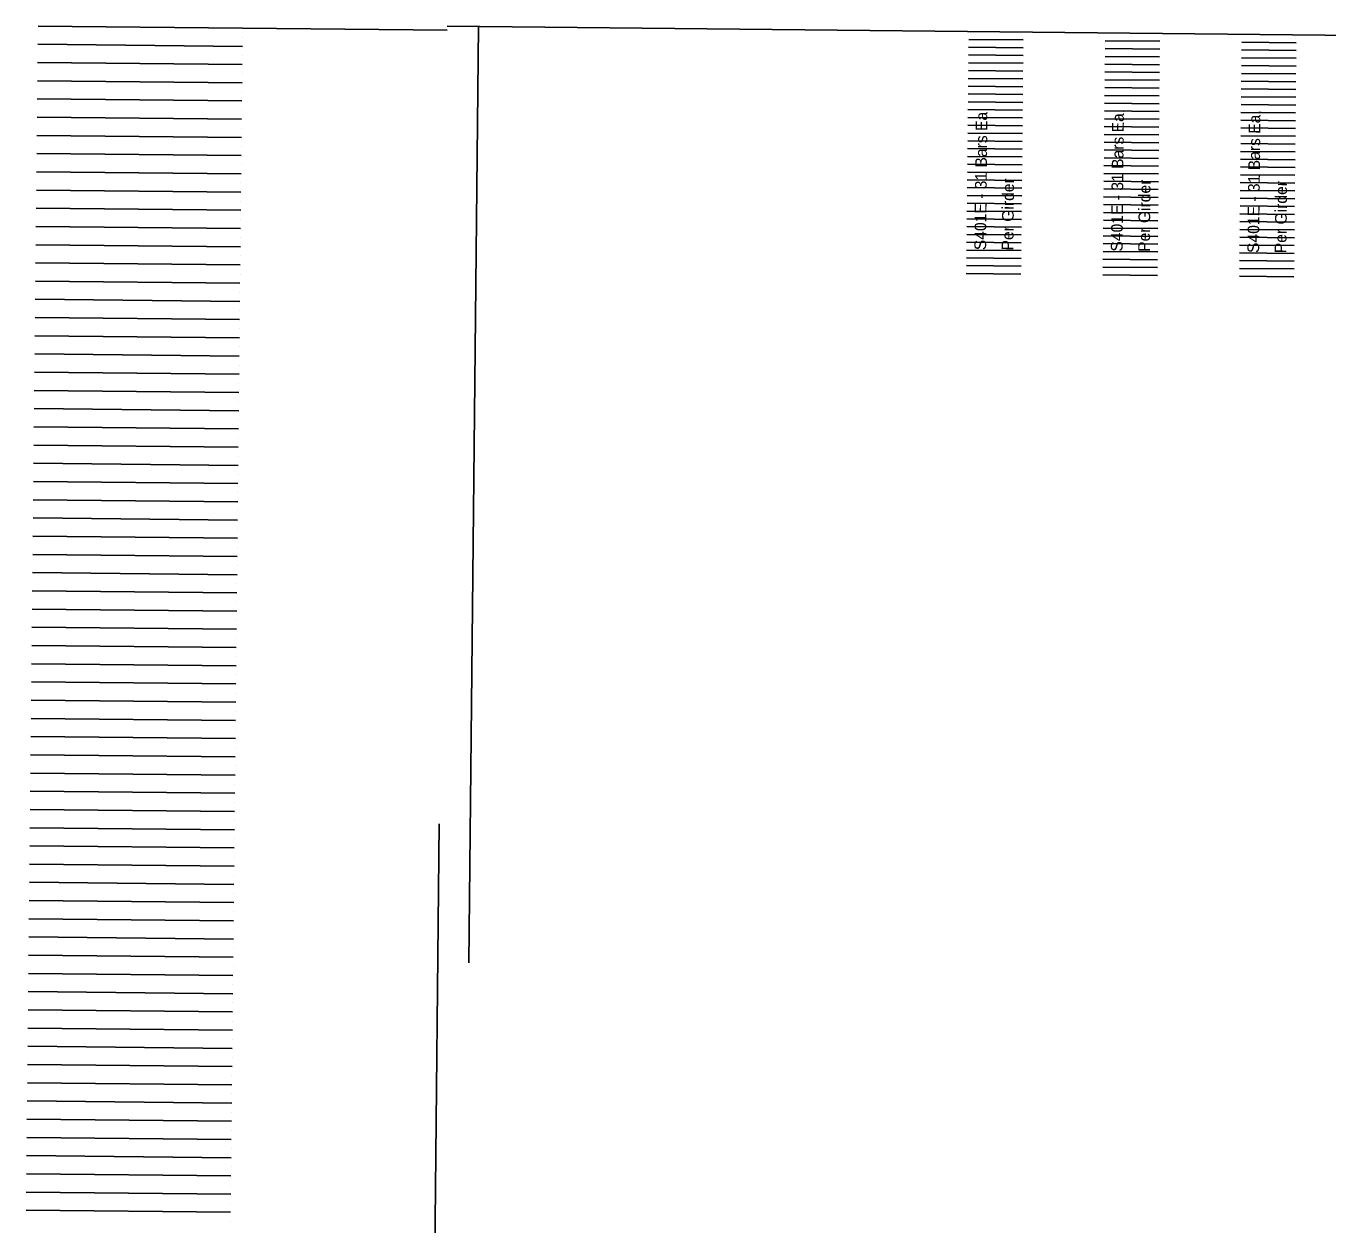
# Model space of a CAD drawing. Extents: x 632547 to 633311, y 380830 to 386139.
# Drawn here: x 633073.6 to 633157.1, y 381343.8 to 381420.6 of the extents above; entities that cross this region are included whole.
import ezdxf

# ---------------------------------------------------------------- set-up
doc = ezdxf.new("R2010")
doc.units = 0
for name, color, linetype in [('B_Border', 7, 'Continuous'), ('R_Border_Scale', 7, 'Continuous'), ('R_Wall', 7, 'Continuous')]:
    doc.layers.add(name, color=color, linetype=linetype)

msp = doc.modelspace()

# ---------------------------------------------------------------- linework, layer by layer
at = {"layer": 'B_Border'}
msp.add_line((633217.685, 381419.389), (633100.631, 381420.573), dxfattribs=at)
at = {"layer": 'R_Border_Scale'}
for p, q in [((633087.518, 381420.455), (633074.406, 381420.588)), ((633100.629, 381420.323), (633087.518, 381420.455)), ((633087.518, 381420.455), (633087.518, 381420.455)), ((633102.631, 381420.552), (633102.024, 381360.555)), ((633087.512, 381419.872), (633087.512, 381419.872)), ((633137.559, 381419.699), (633134.059, 381419.735)), ((633146.309, 381419.611), (633142.809, 381419.646)), ((633087.506, 381419.288), (633074.395, 381419.421)), ((633087.506, 381419.288), (633087.506, 381419.288)), ((633137.549, 381418.699), (633134.049, 381418.735)), ((633137.554, 381419.199), (633134.054, 381419.235)), ((633146.304, 381419.111), (633142.804, 381419.146)), ((633155.053, 381419.022), (633151.553, 381419.058)), ((633155.058, 381419.522), (633151.559, 381419.558)), ((633087.494, 381418.121), (633074.383, 381418.253)), ((633087.494, 381418.121), (633087.494, 381418.121)), ((633087.5, 381418.704), (633087.5, 381418.704)), ((633137.544, 381418.199), (633134.044, 381418.235)), ((633146.294, 381418.111), (633142.794, 381418.146)), ((633146.299, 381418.611), (633142.799, 381418.646)), ((633155.043, 381418.022), (633151.543, 381418.058)), ((633155.048, 381418.522), (633151.548, 381418.558)), ((633087.482, 381416.953), (633074.371, 381417.086)), ((633087.488, 381417.537), (633087.488, 381417.537)), ((633137.534, 381417.199), (633134.034, 381417.235)), ((633137.539, 381417.699), (633134.039, 381417.735)), ((633146.283, 381417.111), (633142.784, 381417.146)), ((633146.289, 381417.611), (633142.789, 381417.646)), ((633155.038, 381417.522), (633151.538, 381417.558)), ((633087.476, 381416.37), (633087.476, 381416.37)), ((633087.482, 381416.953), (633087.482, 381416.953)), ((633137.524, 381416.199), (633134.024, 381416.235)), ((633137.529, 381416.699), (633134.029, 381416.735)), ((633146.278, 381416.611), (633142.779, 381416.646)), ((633155.028, 381416.522), (633151.528, 381416.558)), ((633155.033, 381417.022), (633151.533, 381417.058)), ((633087.47, 381415.786), (633074.359, 381415.919)), ((633087.47, 381415.786), (633087.47, 381415.786)), ((633137.519, 381415.699), (633134.019, 381415.735)), ((633146.268, 381415.611), (633142.768, 381415.646)), ((633146.273, 381416.111), (633142.774, 381416.146)), ((633155.018, 381415.522), (633151.518, 381415.558)), ((633155.023, 381416.022), (633151.523, 381416.058)), ((633087.459, 381414.619), (633074.347, 381414.751)), ((633087.459, 381414.619), (633087.459, 381414.619)), ((633087.465, 381415.202), (633087.465, 381415.202)), ((633137.509, 381414.699), (633134.009, 381414.735)), ((633137.514, 381415.199), (633134.014, 381415.235)), ((633146.258, 381414.611), (633142.758, 381414.646)), ((633146.263, 381415.111), (633142.763, 381415.146)), ((633155.008, 381414.522), (633151.508, 381414.558)), ((633155.013, 381415.022), (633151.513, 381415.058)), ((633087.453, 381414.035), (633087.453, 381414.035)), ((633137.499, 381413.699), (633133.999, 381413.735)), ((633137.504, 381414.199), (633134.004, 381414.235)), ((633146.253, 381414.111), (633142.753, 381414.146)), ((633155.003, 381414.022), (633151.503, 381414.058)), ((633087.447, 381413.451), (633074.336, 381413.584)), ((633087.447, 381413.451), (633087.447, 381413.451)), ((633137.493, 381413.199), (633133.994, 381413.235)), ((633146.243, 381413.111), (633142.743, 381413.146)), ((633146.248, 381413.611), (633142.748, 381413.646)), ((633154.993, 381413.022), (633151.493, 381413.058)), ((633154.998, 381413.522), (633151.498, 381413.558)), ((633087.435, 381412.284), (633074.324, 381412.417)), ((633087.435, 381412.284), (633087.435, 381412.284)), ((633087.441, 381412.868), (633087.441, 381412.868)), ((633137.483, 381412.2), (633133.984, 381412.235)), ((633137.488, 381412.7), (633133.989, 381412.735)), ((633146.233, 381412.111), (633142.733, 381412.146)), ((633146.238, 381412.611), (633142.738, 381412.646)), ((633154.982, 381412.022), (633151.483, 381412.058)), ((633154.988, 381412.522), (633151.488, 381412.558)), ((633087.423, 381411.117), (633074.312, 381411.249)), ((633087.429, 381411.7), (633087.429, 381411.7)), ((633137.473, 381411.2), (633133.973, 381411.235)), ((633137.478, 381411.7), (633133.978, 381411.735)), ((633146.228, 381411.611), (633142.728, 381411.646)), ((633154.977, 381411.523), (633151.478, 381411.558)), ((633087.417, 381410.533), (633087.417, 381410.533)), ((633087.423, 381411.117), (633087.423, 381411.117)), ((633137.468, 381410.7), (633133.968, 381410.735)), ((633146.218, 381410.611), (633142.718, 381410.646)), ((633146.223, 381411.111), (633142.723, 381411.146)), ((633154.967, 381410.523), (633151.467, 381410.558)), ((633154.972, 381411.023), (633151.473, 381411.058)), ((633087.411, 381409.949), (633074.3, 381410.082)), ((633087.411, 381409.949), (633087.411, 381409.949)), ((633137.458, 381409.7), (633133.958, 381409.735)), ((633137.463, 381410.2), (633133.963, 381410.235)), ((633146.208, 381409.611), (633142.708, 381409.647)), ((633146.213, 381410.111), (633142.713, 381410.147)), ((633154.957, 381409.523), (633151.457, 381409.558)), ((633154.962, 381410.023), (633151.462, 381410.058)), ((633087.4, 381408.782), (633074.288, 381408.915)), ((633087.4, 381408.782), (633087.4, 381408.782)), ((633087.405, 381409.366), (633087.405, 381409.366)), ((633137.448, 381408.7), (633133.948, 381408.735)), ((633137.453, 381409.2), (633133.953, 381409.235)), ((633146.203, 381409.111), (633142.703, 381409.147)), ((633154.952, 381409.023), (633151.452, 381409.058)), ((633087.394, 381408.198), (633087.394, 381408.198)), ((633137.443, 381408.2), (633133.943, 381408.235)), ((633146.192, 381408.111), (633142.693, 381408.147)), ((633146.197, 381408.611), (633142.698, 381408.647)), ((633154.942, 381408.023), (633151.442, 381408.058)), ((633154.947, 381408.523), (633151.447, 381408.558)), ((633087.388, 381407.615), (633074.277, 381407.747)), ((633087.388, 381407.615), (633087.388, 381407.615)), ((633137.433, 381407.2), (633133.933, 381407.235)), ((633137.438, 381407.7), (633133.938, 381407.735)), ((633146.182, 381407.111), (633142.683, 381407.147)), ((633146.187, 381407.611), (633142.688, 381407.647)), ((633154.932, 381407.023), (633151.432, 381407.058)), ((633154.937, 381407.523), (633151.437, 381407.558)), ((633087.376, 381406.447), (633074.265, 381406.58)), ((633087.376, 381406.447), (633087.376, 381406.447)), ((633087.382, 381407.031), (633087.382, 381407.031)), ((633137.423, 381406.2), (633133.923, 381406.235)), ((633137.428, 381406.7), (633133.928, 381406.735)), ((633146.177, 381406.611), (633142.677, 381406.647)), ((633154.927, 381406.523), (633151.427, 381406.558)), ((633087.364, 381405.28), (633074.253, 381405.412)), ((633087.37, 381405.863), (633087.37, 381405.863)), ((633137.418, 381405.7), (633133.918, 381405.735)), ((633146.167, 381405.611), (633142.667, 381405.647)), ((633146.172, 381406.111), (633142.672, 381406.147)), ((633154.917, 381405.523), (633151.417, 381405.558)), ((633154.922, 381406.023), (633151.422, 381406.058)), ((633087.358, 381404.696), (633087.358, 381404.696)), ((633087.364, 381405.28), (633087.364, 381405.28)), ((633137.407, 381404.7), (633133.908, 381404.735)), ((633137.413, 381405.2), (633133.913, 381405.235)), ((633146.157, 381404.611), (633142.657, 381404.647)), ((633146.162, 381405.111), (633142.662, 381405.147)), ((633154.907, 381404.523), (633151.407, 381404.558)), ((633154.912, 381405.023), (633151.412, 381405.058)), ((633087.352, 381404.112), (633074.241, 381404.245)), ((633087.352, 381404.112), (633087.352, 381404.112)), ((633087.34, 381402.945), (633074.229, 381403.078)), ((633087.34, 381402.945), (633087.34, 381402.945)), ((633087.346, 381403.529), (633087.346, 381403.529)), ((633087.335, 381402.361), (633087.335, 381402.361)), ((633087.329, 381401.778), (633074.218, 381401.91)), ((633087.329, 381401.778), (633087.329, 381401.778)), ((633087.317, 381400.61), (633074.206, 381400.743)), ((633087.317, 381400.61), (633087.317, 381400.61)), ((633087.323, 381401.194), (633087.323, 381401.194)), ((633087.305, 381399.443), (633074.194, 381399.576)), ((633087.311, 381400.027), (633087.311, 381400.027)), ((633087.299, 381398.859), (633087.299, 381398.859)), ((633087.305, 381399.443), (633087.305, 381399.443)), ((633087.293, 381398.276), (633074.182, 381398.408)), ((633087.293, 381398.276), (633087.293, 381398.276)), ((633087.281, 381397.108), (633074.17, 381397.241)), ((633087.281, 381397.108), (633087.281, 381397.108)), ((633087.287, 381397.692), (633087.287, 381397.692)), ((633087.276, 381396.525), (633087.276, 381396.525)), ((633087.27, 381395.941), (633074.158, 381396.074)), ((633087.27, 381395.941), (633087.27, 381395.941)), ((633087.258, 381394.774), (633074.147, 381394.906)), ((633087.258, 381394.774), (633087.258, 381394.774)), ((633087.264, 381395.357), (633087.264, 381395.357)), ((633087.246, 381393.606), (633074.135, 381393.739)), ((633087.252, 381394.19), (633087.252, 381394.19)), ((633087.24, 381393.023), (633087.24, 381393.023)), ((633087.246, 381393.606), (633087.246, 381393.606)), ((633087.234, 381392.439), (633074.123, 381392.572)), ((633087.234, 381392.439), (633087.234, 381392.439)), ((633087.222, 381391.272), (633074.111, 381391.404)), ((633087.222, 381391.272), (633087.222, 381391.272)), ((633087.228, 381391.855), (633087.228, 381391.855)), ((633087.216, 381390.688), (633087.216, 381390.688)), ((633087.211, 381390.104), (633074.099, 381390.237)), ((633087.205, 381389.521), (633087.205, 381389.521)), ((633087.211, 381390.104), (633087.211, 381390.104)), ((633087.199, 381388.937), (633074.088, 381389.069)), ((633087.199, 381388.937), (633087.199, 381388.937)), ((633087.187, 381387.769), (633074.076, 381387.902)), ((633087.193, 381388.353), (633087.193, 381388.353)), ((633087.181, 381387.186), (633087.181, 381387.186)), ((633087.187, 381387.769), (633087.187, 381387.769)), ((633087.175, 381386.602), (633074.064, 381386.735)), ((633087.175, 381386.602), (633087.175, 381386.602)), ((633087.163, 381385.435), (633074.052, 381385.567)), ((633087.163, 381385.435), (633087.163, 381385.435)), ((633087.169, 381386.018), (633087.169, 381386.018)), ((633087.157, 381384.851), (633087.157, 381384.851)), ((633087.152, 381384.267), (633074.04, 381384.4)), ((633087.146, 381383.684), (633087.146, 381383.684)), ((633087.152, 381384.267), (633087.152, 381384.267)), ((633087.14, 381383.1), (633074.029, 381383.233)), ((633087.14, 381383.1), (633087.14, 381383.1)), ((633087.128, 381381.933), (633074.017, 381382.065)), ((633087.134, 381382.516), (633087.134, 381382.516)), ((633087.122, 381381.349), (633087.122, 381381.349)), ((633087.128, 381381.933), (633087.128, 381381.933)), ((633087.116, 381380.765), (633074.005, 381380.898)), ((633087.116, 381380.765), (633087.116, 381380.765)), ((633087.104, 381379.598), (633073.993, 381379.731)), ((633087.104, 381379.598), (633087.104, 381379.598)), ((633087.11, 381380.182), (633087.11, 381380.182)), ((633087.098, 381379.014), (633087.098, 381379.014)), ((633087.092, 381378.431), (633073.981, 381378.563)), ((633087.087, 381377.847), (633087.087, 381377.847)), ((633087.092, 381378.431), (633087.092, 381378.431)), ((633087.081, 381377.263), (633073.97, 381377.396)), ((633087.081, 381377.263), (633087.081, 381377.263)), ((633087.069, 381376.096), (633073.958, 381376.229)), ((633087.075, 381376.68), (633087.075, 381376.68)), ((633087.063, 381375.512), (633087.063, 381375.512)), ((633087.069, 381376.096), (633087.069, 381376.096)), ((633087.057, 381374.929), (633073.946, 381375.061)), ((633087.057, 381374.929), (633087.057, 381374.929)), ((633087.045, 381373.761), (633073.934, 381373.894)), ((633087.045, 381373.761), (633087.045, 381373.761)), ((633087.051, 381374.345), (633087.051, 381374.345)), ((633087.039, 381373.178), (633087.039, 381373.178)), ((633087.033, 381372.594), (633073.922, 381372.726)), ((633087.028, 381372.01), (633087.028, 381372.01)), ((633087.033, 381372.594), (633087.033, 381372.594)), ((633087.022, 381371.426), (633073.91, 381371.559)), ((633087.022, 381371.426), (633087.022, 381371.426)), ((633087.01, 381370.259), (633073.899, 381370.392)), ((633087.016, 381370.843), (633087.016, 381370.843)), ((633087.004, 381369.675), (633087.004, 381369.675)), ((633087.01, 381370.259), (633087.01, 381370.259)), ((633086.998, 381369.092), (633073.887, 381369.224)), ((633086.998, 381369.092), (633086.998, 381369.092)), ((633100.114, 381369.463), (633099.507, 381309.466)), ((633086.986, 381367.924), (633073.875, 381368.057)), ((633086.986, 381367.924), (633086.986, 381367.924)), ((633086.992, 381368.508), (633086.992, 381368.508)), ((633086.98, 381367.341), (633086.98, 381367.341)), ((633086.974, 381366.757), (633073.863, 381366.89)), ((633086.968, 381366.173), (633086.968, 381366.173)), ((633086.974, 381366.757), (633086.974, 381366.757)), ((633086.963, 381365.59), (633073.851, 381365.722)), ((633086.963, 381365.59), (633086.963, 381365.59)), ((633086.951, 381364.422), (633073.84, 381364.555)), ((633086.957, 381365.006), (633086.957, 381365.006)), ((633086.945, 381363.839), (633086.945, 381363.839)), ((633086.951, 381364.422), (633086.951, 381364.422)), ((633086.939, 381363.255), (633073.828, 381363.388)), ((633086.939, 381363.255), (633086.939, 381363.255)), ((633086.927, 381362.088), (633073.816, 381362.22)), ((633086.927, 381362.088), (633086.927, 381362.088)), ((633086.933, 381362.671), (633086.933, 381362.671)), ((633086.921, 381361.504), (633086.921, 381361.504)), ((633086.915, 381360.92), (633073.804, 381361.053)), ((633086.909, 381360.337), (633086.909, 381360.337)), ((633086.915, 381360.92), (633086.915, 381360.92)), ((633086.904, 381359.753), (633073.792, 381359.886)), ((633086.904, 381359.753), (633086.904, 381359.753)), ((633086.892, 381358.586), (633073.781, 381358.718)), ((633086.898, 381359.169), (633086.898, 381359.169)), ((633086.886, 381358.002), (633086.886, 381358.002)), ((633086.892, 381358.586), (633086.892, 381358.586)), ((633086.88, 381357.418), (633073.769, 381357.551)), ((633086.88, 381357.418), (633086.88, 381357.418)), ((633086.868, 381356.251), (633073.757, 381356.384)), ((633086.868, 381356.251), (633086.868, 381356.251)), ((633086.874, 381356.835), (633086.874, 381356.835)), ((633086.862, 381355.667), (633086.862, 381355.667)), ((633086.856, 381355.084), (633073.745, 381355.216)), ((633086.85, 381354.5), (633086.85, 381354.5)), ((633086.856, 381355.084), (633086.856, 381355.084)), ((633086.844, 381353.916), (633073.733, 381354.049)), ((633086.844, 381353.916), (633086.844, 381353.916)), ((633086.833, 381352.749), (633073.722, 381352.881)), ((633086.839, 381353.332), (633086.839, 381353.332)), ((633086.827, 381352.165), (633086.827, 381352.165)), ((633086.833, 381352.749), (633086.833, 381352.749)), ((633086.821, 381351.581), (633073.71, 381351.714)), ((633086.821, 381351.581), (633086.821, 381351.581)), ((633086.809, 381350.414), (633073.698, 381350.547)), ((633086.809, 381350.414), (633086.809, 381350.414)), ((633086.815, 381350.998), (633086.815, 381350.998)), ((633086.803, 381349.83), (633086.803, 381349.83)), ((633086.797, 381349.247), (633073.686, 381349.379)), ((633086.791, 381348.663), (633086.791, 381348.663)), ((633086.797, 381349.247), (633086.797, 381349.247)), ((633086.785, 381348.079), (633073.674, 381348.212)), ((633086.785, 381348.079), (633086.785, 381348.079)), ((633086.774, 381346.912), (633073.662, 381347.045)), ((633086.78, 381347.496), (633086.78, 381347.496)), ((633086.768, 381346.328), (633086.768, 381346.328)), ((633086.774, 381346.912), (633086.774, 381346.912)), ((633086.762, 381345.745), (633073.651, 381345.877)), ((633086.762, 381345.745), (633086.762, 381345.745)), ((633086.75, 381344.577), (633073.639, 381344.71)), ((633086.75, 381344.577), (633086.75, 381344.577)), ((633086.756, 381345.161), (633086.756, 381345.161)), ((633086.744, 381343.994), (633086.744, 381343.994))]:
    msp.add_line(p, q, dxfattribs=at)

# ---------------------------------------------------------------- texts
at = {"layer": 'R_Wall'}
for s, p in [('S401E - 31 Bars Ea,', (633135.173, 381406.223)), ('S401E - 31 Bars Ea,', (633143.922, 381406.134)), ('S401E - 31 Bars Ea,', (633152.672, 381406.045)), ('Per Girder', (633136.923, 381406.205)), ('Per Girder', (633145.672, 381406.117)), ('Per Girder', (633154.422, 381406.028))]:
    msp.add_text(s, height=0.75, rotation=89.43036, dxfattribs=at).set_placement(p)

doc.saveas('drawing.dxf')
